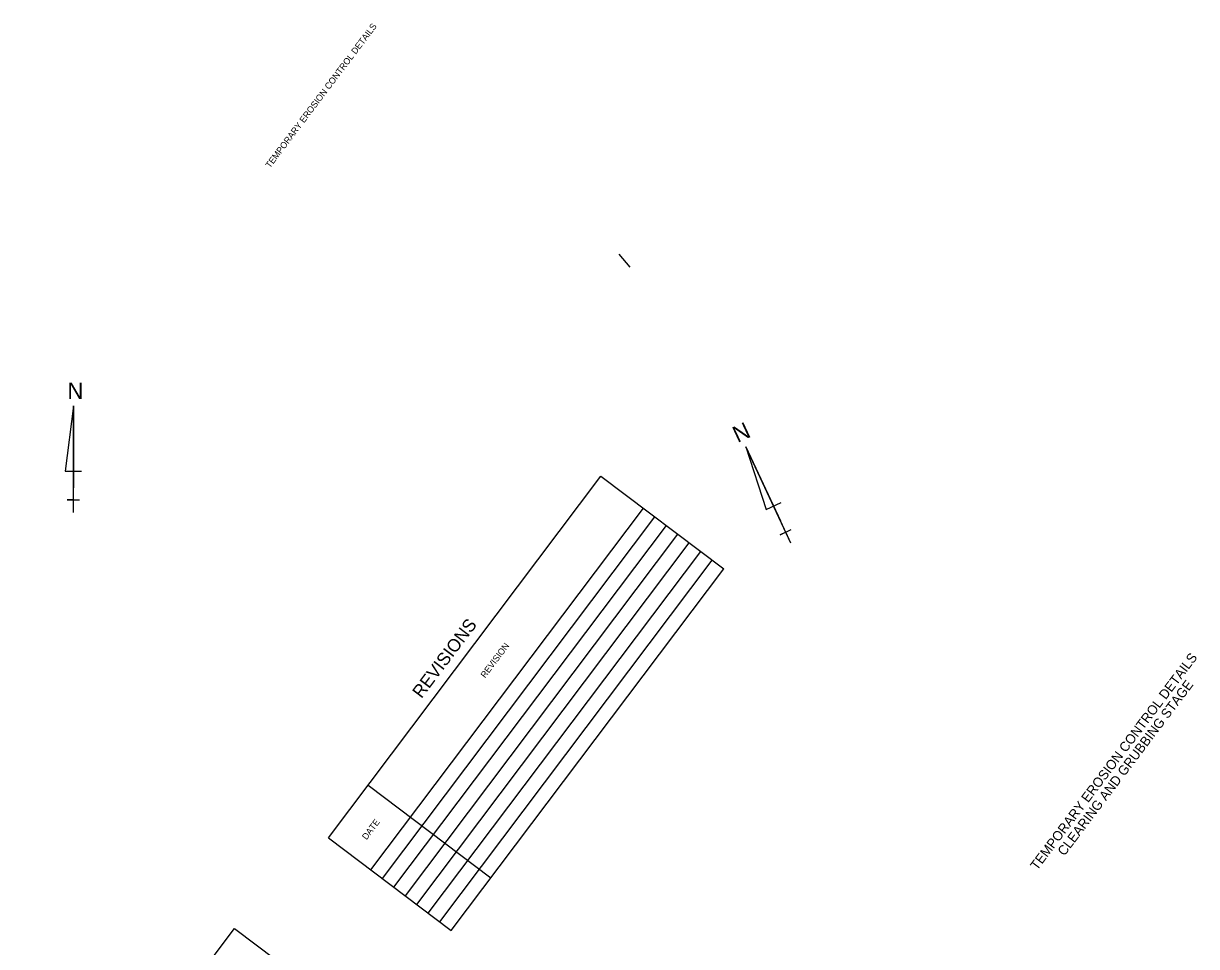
# Model space of a CAD drawing. Extents: x 1713751 to 1715480, y 763628 to 765350.
# Drawn here: x 1714378 to 1715480, y 764484 to 765350 of the extents above; entities that cross this region are included whole.
import ezdxf

# ---------------------------------------------------------------- set-up
doc = ezdxf.new("R2010")
doc.units = 0
for name, color, linetype in [('1', 7, 'Continuous'), ('63', 7, 'Continuous'), ('Default', 7, 'Continuous'), ('G-ANNO-TEXT', 7, 'Continuous')]:
    doc.layers.add(name, color=color, linetype=linetype)

msp = doc.modelspace()

# ---------------------------------------------------------------- linework, layer by layer
at = {"layer": '1'}
msp.add_lwpolyline([(1714337.8, 764184.3), (1714576.6, 764501.1), (1714694.7, 764412.1), (1714455.9, 764095.3)], close=True, dxfattribs=at)
at = {"layer": '63'}
for p, q in [((1714425.4, 764991.6), (1714417.7, 764930.1)), ((1714425.4, 764891.6), (1714425.4, 764991.6)), ((1714425.4, 764991.6), (1714425.4, 764914.7)), ((1715098.9, 764862.6), (1715056.6, 764953.2)), ((1715056.6, 764953.2), (1715089.1, 764883.5)), ((1715056.6, 764953.2), (1715075.7, 764894.2)), ((1714417.7, 764930.1), (1714433.1, 764930.1)), ((1714425.4, 764891.6), (1714425.4, 764914.7)), ((1714425.4, 764903.2), (1714419.6, 764903.2)), ((1714419.6, 764903.2), (1714431.2, 764903.2)), ((1714425.4, 764891.6), (1714425.4, 764903.2)), ((1715075.7, 764894.2), (1715089.6, 764900.7)), ((1715098.9, 764862.6), (1715089.1, 764883.5)), ((1715088.8, 764870.6), (1715099.2, 764875.5)), ((1715094, 764873), (1715088.8, 764870.6)), ((1715098.9, 764862.6), (1715094, 764873))]:
    msp.add_line(p, q, dxfattribs=at)
at = {"layer": 'Default'}
for p, q in [((1714937.4, 765133.9), (1714947.8, 765121.7)), ((1714664.7, 764586.2), (1714920.5, 764925.6)), ((1714920.5, 764925.6), (1715035.9, 764838.6)), ((1714704.6, 764556.1), (1714960.4, 764895.5)), ((1714715.4, 764547.9), (1714971.2, 764887.4)), ((1714726.2, 764539.8), (1714982, 764879.2)), ((1714737, 764531.7), (1714992.7, 764871.1)), ((1714737, 764531.7), (1714992.7, 764871.1)), ((1714747.7, 764523.6), (1715003.5, 764863)), ((1714758.5, 764515.5), (1715014.3, 764854.9)), ((1714769.3, 764507.3), (1715025.1, 764846.7)), ((1714780.1, 764499.2), (1715035.9, 764838.6)), ((1714701.9, 764635.5), (1714817.3, 764548.6)), ((1714664.7, 764586.2), (1714780.1, 764499.2))]:
    msp.add_line(p, q, dxfattribs=at)

# ---------------------------------------------------------------- texts
at = {"layer": '63'}
for rotation, p in [(360, (1714419.8, 764998)), (25, (1715048.8, 764956.6))]:
    msp.add_text('N', height=15.4, rotation=rotation, dxfattribs=at).set_placement(p)
at = {"layer": 'Default'}
for s, height, p in [('REVISIONS', 12, (1714752.1, 764716.3)), ('REVISION', 6, (1714811.8, 764735.7)), ('DATE', 6, (1714700.5, 764583.8))]:
    msp.add_text(s, height=height, rotation=53, dxfattribs=at).set_placement(p)
at = {"layer": 'G-ANNO-TEXT'}
for s, height, p in [('TEMPORARY EROSION CONTROL DETAILS', 6, (1714609.9, 765214.1)), ('TEMPORARY EROSION CONTROL DETAILS', 9, (1715330, 764555.1)), ('CLEARING AND GRUBBING STAGE', 9, (1715355.6, 764568.6))]:
    msp.add_text(s, height=height, rotation=53, dxfattribs=at).set_placement(p)

doc.saveas('drawing.dxf')
